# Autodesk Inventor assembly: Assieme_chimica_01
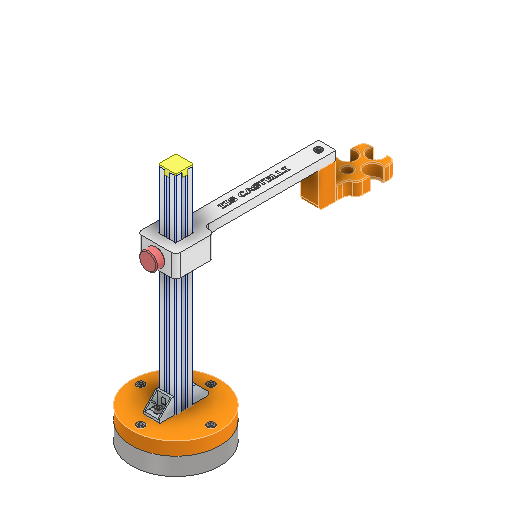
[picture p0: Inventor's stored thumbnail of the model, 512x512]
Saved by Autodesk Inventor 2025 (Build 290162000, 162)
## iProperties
Created: 2025-09
Part Number: Assieme_chimica_01
Document SubType Name: Assembly
Designer: Ryzen5700u
Author: Ryzen5700u
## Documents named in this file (16)
- C:\Users\18907419\Desktop\chimica\Assieme_chimica_01.iam
- C:\Users\18907419\Desktop\chimica\tslot-20x20-3_MIR1.ipt
- C:\Users\18907419\Desktop\chimica\SNSD20x20.ipt
- C:\Users\18907419\Desktop\chimica\base_petg.ipt
- C:\Users\18907419\Desktop\chimica\base_ferro.ipt
- C:\Users\18907419\Desktop\chimica\braccio.ipt
- C:\Users\18907419\Desktop\chimica\tappo_2020.ipt
- C:\Users\18907419\Desktop\chimica\vite_blocco.ipt
- C:\Users\18907419\Desktop\chimica\porta_sensore.ipt
- C:\Users\18907419\Documents\Inventor\Content Center Files\R2025\it-IT\AS 1420\AS 1420 - 1973 - M5 x 20.ipt
- C:\Users\18907419\Documents\Inventor\Content Center Files\R2025\it-IT\AS 1112 (2)\AS 1112 - M4  Tipo 5.ipt
- C:\Users\18907419\Documents\Inventor\Content Center Files\R2025\it-IT\AS 1420\AS 1420 - 1973 - M4 x 8.ipt
- C:\Users\18907419\Documents\Inventor\Content Center Files\R2025\it-IT\AS 1420\AS 1420 - 1973 - M5 x 35.ipt
- C:\Users\18907419\Documents\Inventor\Content Center Files\R2025\it-IT\AS 1420\AS 1420 - 1973 - M4 x 16.ipt
- C:\Users\18907419\Documents\Inventor\Content Center Files\R2025\it-IT\AS 1420\AS 1420 - 1973 - M4 x 30.ipt
- C:\Users\18907419\Desktop\chimica\Slider T-Nut for 2020 - M4\Slider T-Nut for 2020 - M4.ipt
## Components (22 placed, 15 different names)
1. tslot-20x20-3_MIR1:1
2. SNSD20x20:1 — Allineato:1, Allineato:2, Coincidente:1, Coincidente:16
3. SNSD20x20:2 — Allineato:3, Coincidente:2, Allineato:4, Coincidente:13, Coincidente:15
4. base_petg:1
5. base_ferro:1 — Allineato:6
6. braccio:1
7. tappo_2020:1 — Allineato:8
8. vite_blocco:1 — Allineato:9, Coincidente:22
9. porta_sensore:1 — Allineato:10, Coincidente:23, Angolo:2, Rotazionale:3
10. AS 1420 - Metrico M5 x 20:1 — Coincidente:6
11. AS 1420 - Metrico M5 x 20:2 — Coincidente:8
12. AS 1420 - Metrico M5 x 20:3 — Coincidente:10
13. AS 1420 - Metrico M5 x 20:4 — Coincidente:12
14. AS 1112 (2) - Metrico M4  Tipo 5:1
15. AS 1112 (2) - Metrico M4  Tipo 5:2
16. AS 1420 - Metrico M4 x 16:2 — Coincidente:13, Coincidente:14
17. AS 1420 - Metrico M5 x 35:1 — Rotazionale:1
18. AS 1420 - Metrico M4 x 8:4 — Coincidente:15
19. AS 1420 - Metrico M4 x 16:1 — Coincidente:16, Coincidente:17
20. AS 1112 (2) - Metrico M4  Tipo 5:3 — Rotazionale:3
21. AS 1420 - Metrico M4 x 30:1 — Rotazionale:2, Coincidente:23
22. Slider T-Nut for 2020 - M4:1 — Angolo:1, Coincidente:19, Coincidente:20, Coincidente:21
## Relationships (29: Mate 16, Flush 8, RevoluteJoint 3, Angle 2)
- Allineato:1 [Flush]: SNSD20x20:1
- Allineato:2 [Flush]: SNSD20x20:1
- Coincidente:1 [Mate]: SNSD20x20:1
- Allineato:3 [Flush]: SNSD20x20:2
- Coincidente:2 [Mate]: SNSD20x20:2
- Allineato:4 [Flush]: SNSD20x20:2
- Allineato:6 [Flush]: base_ferro:1
- Allineato:8 [Flush]: tappo_2020:1
- Allineato:9 [Flush]: vite_blocco:1
- Allineato:10 [Flush]: porta_sensore:1
- Coincidente:6 [Mate]: AS 1420 - Metrico M5 x 20:1
- Coincidente:8 [Mate]: AS 1420 - Metrico M5 x 20:2
- Coincidente:10 [Mate]: AS 1420 - Metrico M5 x 20:3
- Coincidente:12 [Mate]: AS 1420 - Metrico M5 x 20:4
- Coincidente:13 [Mate]: SNSD20x20:2 ↔ AS 1420 - Metrico M4 x 16:2
- Coincidente:14 [Mate]: AS 1420 - Metrico M4 x 16:2
- Rotazionale:1 [RevoluteJoint]: AS 1420 - Metrico M5 x 35:1
- Coincidente:15 [Mate]: SNSD20x20:2 ↔ AS 1420 - Metrico M4 x 8:4
- Coincidente:16 [Mate]: SNSD20x20:1 ↔ AS 1420 - Metrico M4 x 16:1
- Coincidente:17 [Mate]: AS 1420 - Metrico M4 x 16:1
- Rotazionale:2 [RevoluteJoint]: AS 1420 - Metrico M4 x 30:1
- Angolo:1 [Angle]: Slider T-Nut for 2020 - M4:1
- Coincidente:19 [Mate]: Slider T-Nut for 2020 - M4:1
- Coincidente:20 [Mate]: Slider T-Nut for 2020 - M4:1
- Coincidente:21 [Mate]: Slider T-Nut for 2020 - M4:1
- Coincidente:22 [Mate]: vite_blocco:1
- Coincidente:23 [Mate]: porta_sensore:1 ↔ AS 1420 - Metrico M4 x 30:1
- Angolo:2 [Angle]: porta_sensore:1
- Rotazionale:3 [RevoluteJoint]: porta_sensore:1 ↔ AS 1112 (2) - Metrico M4  Tipo 5:3
